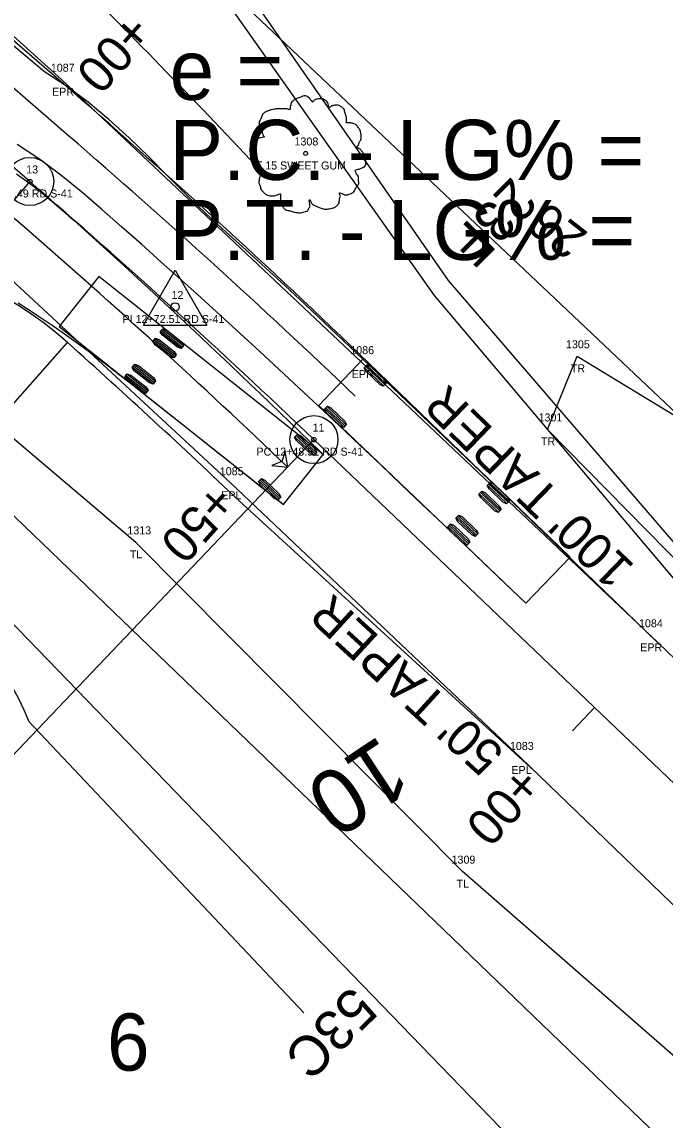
# Model space of a CAD drawing. Extents: x 1812113 to 1819860, y 1177290 to 1181185.
# Drawn here: x 1813849.5 to 1813930, y 1178506.5 to 1178643.7 of the extents above; entities that cross this region are included whole.
import ezdxf

# ---------------------------------------------------------------- set-up
doc = ezdxf.new("R2010")
doc.units = 0
for name, color, linetype in [('RD_EX_DV_Prop', 7, 'Continuous'), ('RD_EX_DV_TX_Prop', 7, 'Continuous'), ('RD_EX_Road', 7, 'Continuous'), ('RD_EX_Road_txCode', 7, 'Continuous'), ('RD_EX_VEG', 7, 'Continuous'), ('RD_EX_VEG_txCode', 7, 'Continuous'), ('RD_HC_CL', 7, 'Continuous'), ('RD_HC_Data', 7, 'Continuous'), ('RD_HC_Data_Tic', 7, 'Continuous'), ('RD_HC_TX_StaOther', 7, 'Continuous'), ('RD_HC_txCode', 7, 'Continuous'), ('RD_PD_ALT1_LnLine', 7, 'Continuous'), ('RD_PD_ALT1_TrvlWay', 7, 'Continuous'), ('RD_PD_CstnLmt', 7, 'Continuous'), ('RD_PD_DR_ErosCtrl', 7, 'Continuous'), ('RD_PD_Final_TnTmp', 7, 'Continuous'), ('RD_PD_PatLn1', 7, 'Continuous'), ('RD_Sketch10', 7, 'Continuous'), ('RD_Sketch6', 7, 'Continuous'), ('RD_SMD_Locator', 7, 'Continuous')]:
    doc.layers.add(name, color=color, linetype=linetype)

msp = doc.modelspace()

# ---------------------------------------------------------------- linework, layer by layer
at = {"layer": 'RD_EX_DV_Prop'}
for p, q in [((1814011.17, 1178519.35), (1813854.67, 1178667.32)), ((1814007.16, 1178429.49), (1813829.73, 1178600.06))]:
    msp.add_line(p, q, dxfattribs=at)
at = {"layer": 'RD_EX_Road'}
for p, q in [((1813875.67, 1178586.1), (1813838.32, 1178620.7)), ((1813911.94, 1178551.77), (1813875.67, 1178586.1)), ((1813949.15, 1178515.86), (1813911.94, 1178551.77))]:
    msp.add_line(p, q, dxfattribs=at)
msp.add_lwpolyline([(1814076.45, 1178427.4), (1814038.86, 1178461.87), (1814001.83, 1178496.62), (1813965.15, 1178531.54), (1813928.08, 1178567.1), (1813892.01, 1178601.23), (1813854.54, 1178636.51), (1813817.44, 1178670.03), (1813779.87, 1178701.64)], dxfattribs=at)
at = {"layer": 'RD_EX_VEG'}
for points in [[(1813964.65, 1178448.48), (1813984.61, 1178463.55), (1813943.71, 1178503.46), (1813904.65, 1178537.57), (1813863.79, 1178578.71), (1813833.99, 1178603.93), (1813823.24, 1178594.53), (1813964.65, 1178448.48)], [(1813986.62, 1178560.85), (1813980.11, 1178526.91), (1813915.24, 1178592.82), (1813918.96, 1178601.96), (1813986.62, 1178560.85)]]:
    msp.add_lwpolyline(points, dxfattribs=at)
for centre, radius in [((1813885.01, 1178627.3), 0.25), ((1813885, 1178627.28), 0.0001)]:
    msp.add_circle(centre, radius, dxfattribs=at)
for points in [[(1813885.14, 1178634.47), (1813884.84, 1178634.49), (1813884.52, 1178634.39), (1813884.27, 1178634.29), (1813884.04, 1178634.22), (1813883.82, 1178634.12), (1813883.52, 1178633.94), (1813883.29, 1178633.74), (1813883.17, 1178633.49), (1813883.12, 1178633.27), (1813883.07, 1178632.99), (1813883.07, 1178632.82), (1813882.94, 1178632.79), (1813882.79, 1178632.82), (1813882.54, 1178632.89), (1813882.29, 1178632.89), (1813882.04, 1178632.89), (1813881.69, 1178632.87), (1813881.34, 1178632.87), (1813881.07, 1178632.82), (1813880.74, 1178632.77), (1813880.37, 1178632.64), (1813880.02, 1178632.52), (1813879.72, 1178632.27), (1813879.47, 1178631.8), (1813879.34, 1178631.45), (1813879.19, 1178631.2), (1813879.34, 1178630.75), (1813879.52, 1178630.4), (1813879.54, 1178630.2), (1813879.62, 1178629.77), (1813879.72, 1178629.55), (1813879.84, 1178629.35), (1813879.77, 1178629.32), (1813879.39, 1178629.27), (1813879.09, 1178629.17), (1813878.67, 1178628.95), (1813878.44, 1178628.72), (1813878.34, 1178628.4), (1813878.32, 1178628.05), (1813878.22, 1178627.85), (1813878.14, 1178627.57), (1813878.12, 1178627.5), (1813878.07, 1178627.17), (1813878.17, 1178626.72), (1813878.19, 1178626.37), (1813878.32, 1178626.15), (1813878.47, 1178625.97), (1813878.64, 1178625.72), (1813879.04, 1178625.5), (1813879.37, 1178625.4), (1813879.57, 1178625.37), (1813879.39, 1178624.87), (1813879.34, 1178624.52), (1813879.22, 1178624.12), (1813879.22, 1178624.05), (1813879.17, 1178623.57), (1813879.32, 1178623.25), (1813879.39, 1178622.87), (1813879.57, 1178622.65), (1813879.84, 1178622.35), (1813880.17, 1178622.12), (1813880.67, 1178622), (1813881.07, 1178622.02), (1813881.64, 1178622.2), (1813881.89, 1178622.27), (1813881.87, 1178622.1), (1813881.89, 1178621.72), (1813881.89, 1178621.3), (1813882.04, 1178620.98), (1813882.14, 1178620.7), (1813882.29, 1178620.45), (1813882.62, 1178620.23), (1813883.02, 1178620.15), (1813883.44, 1178620), (1813883.89, 1178619.93), (1813884.39, 1178619.9), (1813884.99, 1178620.05), (1813885.27, 1178620.18), (1813885.37, 1178620.35), (1813885.57, 1178620.73), (1813885.52, 1178620.95), (1813885.54, 1178621.55), (1813885.64, 1178621.37), (1813885.82, 1178621.02), (1813886.32, 1178620.73), (1813886.72, 1178620.55), (1813887.19, 1178620.4), (1813887.49, 1178620.33), (1813887.96, 1178620.4), (1813888.34, 1178620.48), (1813888.71, 1178620.6), (1813889.01, 1178620.88), (1813889.19, 1178621.15), (1813889.24, 1178621.42), (1813889.31, 1178621.8), (1813889.36, 1178621.97)], [(1813889.36, 1178621.97), (1813889.29, 1178622.15), (1813889.24, 1178622.4), (1813889.31, 1178622.37), (1813889.49, 1178622.32), (1813889.76, 1178622.2), (1813889.99, 1178622.12), (1813890.31, 1178622.15), (1813890.59, 1178622.25), (1813891.04, 1178622.52), (1813891.31, 1178623), (1813891.59, 1178623.4), (1813891.66, 1178623.72), (1813891.61, 1178623.95), (1813891.59, 1178624.45), (1813891.39, 1178624.7), (1813891.34, 1178624.82), (1813891.24, 1178625.22), (1813891.31, 1178625.27), (1813891.59, 1178625.32), (1813891.96, 1178625.45), (1813892.24, 1178625.57), (1813892.46, 1178625.75), (1813892.54, 1178625.97), (1813892.51, 1178626.37), (1813892.56, 1178626.77), (1813892.49, 1178626.92), (1813892.39, 1178627.07), (1813892.31, 1178627.27), (1813892.16, 1178627.42), (1813892.06, 1178627.57), (1813891.96, 1178627.67), (1813891.84, 1178627.82), (1813891.66, 1178627.95), (1813891.51, 1178628), (1813891.46, 1178628.15), (1813891.61, 1178628.35), (1813891.66, 1178628.45), (1813891.69, 1178628.67), (1813891.91, 1178629.02), (1813891.96, 1178629.42), (1813891.91, 1178629.85), (1813891.86, 1178630.12), (1813891.71, 1178630.4), (1813891.51, 1178630.65), (1813891.39, 1178630.82), (1813891.21, 1178630.95), (1813890.89, 1178631.07), (1813890.64, 1178631.12), (1813890.29, 1178631.12), (1813890.09, 1178631.17), (1813890.11, 1178631.22), (1813890.11, 1178631.37), (1813890.11, 1178631.65), (1813890.04, 1178632.1), (1813889.89, 1178632.59), (1813889.89, 1178632.62), (1813889.79, 1178632.87), (1813889.56, 1178633.07), (1813889.39, 1178633.17), (1813889.19, 1178633.29), (1813888.94, 1178633.32), (1813888.64, 1178633.32), (1813888.36, 1178633.27), (1813888.16, 1178633.17), (1813887.99, 1178633.04), (1813887.91, 1178633.19), (1813887.82, 1178633.49), (1813887.77, 1178633.64), (1813887.62, 1178633.82), (1813887.39, 1178634.02), (1813886.94, 1178634.14), (1813886.32, 1178634.07), (1813886.02, 1178633.87), (1813885.87, 1178633.69), (1813885.82, 1178633.82), (1813885.62, 1178634.02), (1813885.52, 1178634.19), (1813885.34, 1178634.32), (1813885.19, 1178634.42), (1813885.09, 1178634.47)]]:
    msp.add_spline(points, degree=3, dxfattribs=at)
at = {"layer": 'RD_HC_CL'}
for p, q in [((1813850.52, 1178623.8), (1813755.38, 1178705.86)), ((1813965.88, 1178515.37), (1813886.05, 1178591.55))]:
    msp.add_line(p, q, dxfattribs=at)
msp.add_arc((1813226.77, 1177900.71), 954.94, 46.33932, 49.21843, dxfattribs=at)
at = {"layer": 'RD_HC_Data'}
for p, q in [((1813850.52, 1178623.8), (1813773.78, 1178534.84)), ((1813864.72, 1178605.83), (1813868.69, 1178612.71)), ((1813868.69, 1178612.71), (1813872.66, 1178605.83)), ((1813864.72, 1178605.83), (1813872.66, 1178605.83)), ((1813886.05, 1178591.55), (1813805.93, 1178507.6))]:
    msp.add_line(p, q, dxfattribs=at)
for centre, radius in [((1813850.52, 1178623.8), 3), ((1813850.52, 1178623.8), 0.282), ((1813868.69, 1178608.12), 0.529), ((1813886.05, 1178591.55), 3), ((1813886.05, 1178591.55), 0.282)]:
    msp.add_circle(centre, radius, dxfattribs=at)
at = {"layer": 'RD_HC_Data_Tic'}
msp.add_line((1813921.14, 1178558.06), (1813918.38, 1178555.17), dxfattribs=at)
at = {"layer": 'RD_PD_ALT1_LnLine'}
msp.add_line((1813958.96, 1178568.72), (1813854.67, 1178667.32), dxfattribs=at)
at = {"layer": 'RD_PD_ALT1_TrvlWay'}
for p, q in [((1813855.7, 1178635.17), (1813779.98, 1178700.49)), ((1813928.97, 1178566.25), (1813894.1, 1178599.98)), ((1813913.6, 1178550.18), (1813876.7, 1178583.89))]:
    msp.add_line(p, q, dxfattribs=at)
for centre, radius, start, end in [((1813221.84, 1177904.96), 966.94, 45.95392, 49.04069), ((1813825.26, 1178570.12), 45, 48.2018, 123.5168), ((1813226.77, 1177900.71), 942.94, 46.42874, 48.20181)]:
    msp.add_arc(centre, radius, start, end, dxfattribs=at)
at = {"layer": 'RD_PD_CstnLmt'}
for p, q in [((1813901.12, 1178609.56), (1813870.71, 1178652.58)), ((1813933.62, 1178571.14), (1813901.12, 1178609.56)), ((1813884.77, 1178519.95), (1813850.45, 1178556.29))]:
    msp.add_line(p, q, dxfattribs=at)
msp.add_arc((1813815.82, 1178542.33), 37.34, 21.9591, 97.2081, dxfattribs=at)
at = {"layer": 'RD_PD_DR_ErosCtrl'}
for p, q in [((1813902.89, 1178611.42), (1813872.68, 1178654.86)), ((1813935.91, 1178573.07), (1813902.89, 1178611.42))]:
    msp.add_line(p, q, dxfattribs=at)
at = {"layer": 'RD_PD_Final_TnTmp'}
msp.add_line((1813825.29, 1178570.08), (1813855.25, 1178603.67), dxfattribs=at)
at = {"layer": 'RD_PD_PatLn1'}
msp.add_arc((1813164.74, 1177954.39), 980.13, 43.10273, 45.13965, dxfattribs=at)
at = {"layer": 'RD_Sketch10'}
for p, q in [((1813859.16, 1178611.94), (1813854.19, 1178605.67)), ((1813887.21, 1178589.7), (1813859.16, 1178611.94)), ((1813854.19, 1178605.67), (1813882.24, 1178583.43)), ((1813866.87, 1178605.03), (1813869.48, 1178602.96)), ((1813867, 1178605.2), (1813869.61, 1178603.12)), ((1813867.13, 1178605.36), (1813869.74, 1178603.29)), ((1813865.94, 1178603.86), (1813868.55, 1178601.79)), ((1813866.07, 1178604.02), (1813868.68, 1178601.95)), ((1813866.2, 1178604.18), (1813868.81, 1178602.11)), ((1813863.35, 1178600.59), (1813865.96, 1178598.52)), ((1813863.48, 1178600.76), (1813866.09, 1178598.68)), ((1813863.61, 1178600.92), (1813866.22, 1178598.85)), ((1813862.42, 1178599.42), (1813865.03, 1178597.35)), ((1813862.55, 1178599.58), (1813865.16, 1178597.51)), ((1813862.68, 1178599.74), (1813865.29, 1178597.67)), ((1813886.09, 1178589.6), (1813883.67, 1178591.9)), ((1813886.23, 1178589.75), (1813883.82, 1178592.05)), ((1813886.37, 1178589.9), (1813883.96, 1178592.2)), ((1813882.24, 1178583.43), (1813887.21, 1178589.7)), ((1813887.21, 1178589.7), (1813887.21, 1178589.7)), ((1813881.57, 1178584.03), (1813879.17, 1178586.34)), ((1813881.72, 1178584.18), (1813879.31, 1178586.49)), ((1813881.86, 1178584.33), (1813879.45, 1178586.64))]:
    msp.add_line(p, q, dxfattribs=at)
for points in [[(1813848.85, 1178624.76), (1813850.38, 1178623.69), (1813851.86, 1178622.56), (1813853.28, 1178621.36), (1813854.68, 1178620.13), (1813856.06, 1178618.91), (1813857.43, 1178617.69), (1813858.78, 1178616.47), (1813860.13, 1178615.25), (1813861.46, 1178614.04), (1813862.78, 1178612.83), (1813864.09, 1178611.62), (1813865.4, 1178610.41), (1813866.69, 1178609.21), (1813867.98, 1178608.01), (1813869.27, 1178606.81), (1813870.54, 1178605.62), (1813871.81, 1178604.42), (1813873.08, 1178603.23), (1813874.34, 1178602.04), (1813875.6, 1178600.85), (1813876.85, 1178599.66), (1813878.09, 1178598.47), (1813879.34, 1178597.29), (1813880.58, 1178596.1), (1813881.81, 1178594.91), (1813883.05, 1178593.73), (1813884.28, 1178592.54), (1813885.5, 1178591.36), (1813886.72, 1178590.17), (1813887.21, 1178589.7)], [(1813849.05, 1178608.64), (1813850.12, 1178607.96), (1813851.2, 1178607.26), (1813852.31, 1178606.53), (1813853.43, 1178605.76), (1813854.58, 1178604.97), (1813855.74, 1178604.15), (1813856.92, 1178603.3), (1813858.1, 1178602.43), (1813859.3, 1178601.54), (1813860.5, 1178600.63), (1813861.7, 1178599.7), (1813862.91, 1178598.76), (1813864.13, 1178597.8), (1813865.35, 1178596.83), (1813866.58, 1178595.85), (1813867.82, 1178594.87), (1813869.06, 1178593.88), (1813870.31, 1178592.89), (1813871.57, 1178591.9), (1813872.82, 1178590.9), (1813874.09, 1178589.9), (1813875.35, 1178588.89), (1813876.62, 1178587.89), (1813877.9, 1178586.88), (1813879.17, 1178585.87), (1813880.45, 1178584.85), (1813881.73, 1178583.84), (1813882.24, 1178583.43)]]:
    msp.add_lwpolyline(points, dxfattribs=at)
for points in [[(1813866.84, 1178604.99), (1813867.16, 1178605.4), (1813867.62, 1178605.23), (1813869.51, 1178603.74), (1813869.77, 1178603.33), (1813869.45, 1178602.92), (1813868.99, 1178603.09), (1813867.11, 1178604.58)], [(1813865.91, 1178603.82), (1813866.23, 1178604.22), (1813866.69, 1178604.06), (1813868.57, 1178602.57), (1813868.84, 1178602.15), (1813868.52, 1178601.75), (1813868.06, 1178601.91), (1813866.18, 1178603.4)], [(1813863.32, 1178600.55), (1813863.64, 1178600.96), (1813864.1, 1178600.79), (1813865.98, 1178599.3), (1813866.25, 1178598.89), (1813865.93, 1178598.48), (1813865.47, 1178598.65), (1813863.59, 1178600.14)], [(1813862.39, 1178599.38), (1813862.71, 1178599.78), (1813863.17, 1178599.62), (1813865.05, 1178598.13), (1813865.32, 1178597.71), (1813865, 1178597.31), (1813864.53, 1178597.47), (1813862.65, 1178598.96)], [(1813886.41, 1178589.94), (1813886.05, 1178589.56), (1813885.61, 1178589.77), (1813883.87, 1178591.43), (1813883.64, 1178591.86), (1813884, 1178592.24), (1813884.44, 1178592.03), (1813886.18, 1178590.38)], [(1813882.77, 1178588.12), (1813882.46, 1178590.09), (1813882.05, 1178588.81), (1813880.78, 1178588.33)], [(1813881.9, 1178584.37), (1813881.54, 1178584), (1813881.09, 1178584.2), (1813879.36, 1178585.86), (1813879.13, 1178586.3), (1813879.49, 1178586.68), (1813879.93, 1178586.47), (1813881.67, 1178584.81)]]:
    msp.add_lwpolyline(points, close=True, dxfattribs=at)
for centre, radius, start, end in [((1813826.94, 1178591.63), 35, 49.0206, 123.5168), ((1813226.77, 1177900.71), 950.19, 46.33932, 49.02058)]:
    msp.add_arc(centre, radius, start, end, dxfattribs=at)
at = {"layer": 'RD_Sketch6'}
for p, q in [((1813855.41, 1178629.48), (1813847.72, 1178636.12)), ((1813892.18, 1178601.6), (1813886.66, 1178595.81)), ((1813918.08, 1178576.88), (1813892.18, 1178601.6)), ((1813892.35, 1178600.57), (1813894.76, 1178598.27)), ((1813892.49, 1178600.72), (1813894.91, 1178598.42)), ((1813892.64, 1178600.87), (1813895.05, 1178598.57)), ((1813886.66, 1178595.81), (1813912.56, 1178571.1)), ((1813886.66, 1178595.81), (1813886.66, 1178595.81)), ((1813887.4, 1178595.39), (1813889.81, 1178593.09)), ((1813887.55, 1178595.54), (1813889.96, 1178593.24)), ((1813887.69, 1178595.69), (1813890.1, 1178593.39)), ((1813910.17, 1178583.57), (1813907.76, 1178585.87)), ((1813910.32, 1178583.72), (1813907.9, 1178586.02)), ((1813910.46, 1178583.87), (1813908.05, 1178586.17)), ((1813909.14, 1178582.48), (1813906.72, 1178584.78)), ((1813909.28, 1178582.63), (1813906.87, 1178584.93)), ((1813909.42, 1178582.78), (1813907.01, 1178585.08)), ((1813906.26, 1178579.47), (1813903.85, 1178581.77)), ((1813906.4, 1178579.62), (1813903.99, 1178581.92)), ((1813906.55, 1178579.77), (1813904.14, 1178582.07)), ((1813905.22, 1178578.38), (1813902.81, 1178580.68)), ((1813905.37, 1178578.53), (1813902.96, 1178580.83)), ((1813905.51, 1178578.68), (1813903.1, 1178580.98)), ((1813912.56, 1178571.1), (1813918.08, 1178576.88))]:
    msp.add_line(p, q, dxfattribs=at)
for points in [[(1813918.08, 1178576.88), (1813915.49, 1178579.36), (1813912.91, 1178581.83), (1813910.32, 1178584.31), (1813907.74, 1178586.79), (1813905.15, 1178589.26), (1813902.56, 1178591.74), (1813899.97, 1178594.21), (1813897.37, 1178596.67), (1813894.77, 1178599.13), (1813892.18, 1178601.6), (1813892.18, 1178601.6), (1813892.18, 1178601.6), (1813889.76, 1178603.9), (1813887.33, 1178606.19), (1813884.9, 1178608.47), (1813882.45, 1178610.75), (1813879.99, 1178613.01), (1813877.53, 1178615.27), (1813875.05, 1178617.52), (1813872.57, 1178619.76), (1813870.15, 1178622.08), (1813867.77, 1178624.47), (1813865.39, 1178626.88), (1813862.95, 1178629.25), (1813860.42, 1178631.53), (1813857.81, 1178633.69), (1813855.11, 1178635.7), (1813852.38, 1178637.52), (1813849.78, 1178639.66), (1813847.18, 1178641.83)], [(1813912.56, 1178571.1), (1813909.97, 1178573.57), (1813907.38, 1178576.04), (1813904.79, 1178578.51), (1813902.2, 1178580.98), (1813899.6, 1178583.45), (1813897.01, 1178585.92), (1813894.41, 1178588.39), (1813891.81, 1178590.85), (1813889.21, 1178593.3), (1813886.6, 1178595.75), (1813886.6, 1178595.75), (1813884.16, 1178598.02), (1813881.72, 1178600.29), (1813879.27, 1178602.55), (1813876.82, 1178604.8), (1813874.36, 1178607.05), (1813871.9, 1178609.29), (1813869.43, 1178611.51), (1813866.95, 1178613.73), (1813864.47, 1178615.95), (1813861.99, 1178618.15), (1813859.49, 1178620.35), (1813856.97, 1178622.52), (1813854.39, 1178624.61), (1813851.73, 1178626.6), (1813848.93, 1178628.44)]]:
    msp.add_lwpolyline(points, dxfattribs=at)
for points in [[(1813892.32, 1178600.53), (1813892.67, 1178600.91), (1813893.12, 1178600.7), (1813894.86, 1178599.05), (1813895.09, 1178598.61), (1813894.73, 1178598.23), (1813894.28, 1178598.44), (1813892.54, 1178600.1)], [(1813887.37, 1178595.35), (1813887.73, 1178595.73), (1813888.17, 1178595.52), (1813889.91, 1178593.86), (1813890.14, 1178593.42), (1813889.78, 1178593.05), (1813889.33, 1178593.26), (1813887.6, 1178594.91)], [(1813910.49, 1178583.9), (1813910.14, 1178583.53), (1813909.69, 1178583.74), (1813907.95, 1178585.39), (1813907.72, 1178585.83), (1813908.08, 1178586.21), (1813908.53, 1178586), (1813910.27, 1178584.34)], [(1813909.46, 1178582.82), (1813909.1, 1178582.44), (1813908.65, 1178582.65), (1813906.92, 1178584.31), (1813906.69, 1178584.74), (1813907.05, 1178585.12), (1813907.49, 1178584.91), (1813909.23, 1178583.25)], [(1813906.58, 1178579.8), (1813906.22, 1178579.43), (1813905.78, 1178579.64), (1813904.04, 1178581.29), (1813903.81, 1178581.73), (1813904.17, 1178582.11), (1813904.62, 1178581.9), (1813906.35, 1178580.24)], [(1813905.55, 1178578.72), (1813905.19, 1178578.34), (1813904.74, 1178578.55), (1813903.01, 1178580.21), (1813902.78, 1178580.64), (1813903.14, 1178581.02), (1813903.58, 1178580.81), (1813905.32, 1178579.16)]]:
    msp.add_lwpolyline(points, close=True, dxfattribs=at)
msp.add_arc((1813226.77, 1177900.71), 962.44, 46.33932, 49.21843, dxfattribs=at)
at = {"layer": 'RD_SMD_Locator'}
for centre in [(1813854.54, 1178636.51), (1813850.52, 1178623.8), (1813868.69, 1178608.12), (1813918.96, 1178601.96), (1813892.01, 1178601.23), (1813915.24, 1178592.82), (1813886.05, 1178591.55), (1813875.67, 1178586.1), (1813863.79, 1178578.71), (1813928.08, 1178567.1), (1813911.94, 1178551.77), (1813904.65, 1178537.57)]:
    msp.add_circle(centre, 0.001, dxfattribs=at)

# ---------------------------------------------------------------- texts
at = {"layer": 'RD_EX_DV_TX_Prop'}
msp.add_text('6', height=7.14, dxfattribs=at).set_placement((1813860.18, 1178512.71))
at = {"layer": 'RD_EX_Road_txCode'}
for s, p in [('1087', (1813853.15, 1178637.51)), ('EPR', (1813853.31, 1178634.51)), ('1086', (1813890.6, 1178602.23)), ('EPR', (1813890.78, 1178599.23)), ('1085', (1813874.28, 1178587.1)), ('EPL', (1813874.46, 1178584.1)), ('1084', (1813926.7, 1178568.1)), ('EPR', (1813926.86, 1178565.1)), ('1083', (1813910.56, 1178552.77)), ('EPL', (1813910.74, 1178549.77))]:
    msp.add_text(s, height=1, dxfattribs=at).set_placement(p)
at = {"layer": 'RD_EX_VEG_txCode'}
for s, p in [('1308', (1813883.62, 1178628.3)), ('T 15 SWEET GUM', (1813878.77, 1178625.3)), ('1305', (1813917.57, 1178602.96)), ('TR', (1813918.17, 1178599.96)), ('1301', (1813914.14, 1178593.82)), ('TR', (1813914.44, 1178590.82)), ('1313', (1813862.72, 1178579.71)), ('TL', (1813863.02, 1178576.71)), ('1309', (1813903.26, 1178538.57)), ('TL', (1813903.88, 1178535.57))]:
    msp.add_text(s, height=1, dxfattribs=at).set_placement(p)
at = {"layer": 'RD_HC_TX_StaOther'}
for s, p in [('e = ', (1813868, 1178634)), ('P.C. - LG% = ', (1813868, 1178624)), ('P.T. - LG% = ', (1813868, 1178614))]:
    msp.add_text(s, height=7.5, dxfattribs=at).set_placement(p)
msp.add_text('10', height=8, rotation=213.5168, dxfattribs=at).set_placement((1813894.38, 1178554.73))
at = {"layer": 'RD_HC_txCode'}
for s, p in [('13', (1813850.07, 1178624.8)), ('PT 12+96.49 RD S-41', (1813842.7, 1178621.8)), ('12', (1813868.24, 1178609.12)), ('PI 12+72.51 RD S-41', (1813862.11, 1178606.12)), ('11', (1813885.88, 1178592.55)), ('PC 12+48.51 RD S-41', (1813878.86, 1178589.55))]:
    msp.add_text(s, height=1, dxfattribs=at).set_placement(p)
at = {"layer": 'RD_PD_ALT1_TrvlWay'}
for s, rotation, p in [('+00', 228.1577, (1813862.86, 1178645.08)), ("100' TAPER", 135.9032, (1813926.3, 1178575.74)), ('+50', 228.1577, (1813873.39, 1178586.38)), ("50' TAPER", 137.5348, (1813910.05, 1178552.54)), ('+00', 228.1577, (1813911.59, 1178551.04))]:
    msp.add_text(s, height=4.5, rotation=rotation, dxfattribs=at).set_placement(p)
at = {"layer": 'RD_PD_CstnLmt'}
for s, p in [('23F', (1813910.84, 1178624.53)), ('53C', (1813890.8, 1178523.46))]:
    msp.add_text(s, height=5, rotation=224.8048, dxfattribs=at).set_placement(p)
at = {"layer": 'RD_PD_DR_ErosCtrl'}
msp.add_text('26', height=4.5, rotation=141.9841, dxfattribs=at).set_placement((1813920.5, 1178617.3))

doc.saveas('drawing.dxf')
